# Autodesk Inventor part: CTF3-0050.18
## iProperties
Shininess: 64.0
Length Units: 11269
Angle Units: 11279
Time Units: 11290
Mass Units: 11283
Length Display Precision: 3
Angle Display Precision: 2
Compacted: True
Part Number: CTF3-0050.18
Document SubType Name: Modeling
Created: 2004-01
Designer: Lollo
Density: 0.0
Volumn: 0.0
Area: 0.0
PropertySet Name: Model Information
Control State: 0
Master: False
Checked Out: False
Author: Lollo
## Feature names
1. Estrusione1 [Extrusion]
2. Smusso1 [Chamfer]
3. Estrusione2 [Extrusion]
